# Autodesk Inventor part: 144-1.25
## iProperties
Created: 2007-06
Part Number: 144-1.25
Document SubType Name: Modeling
Designer: btaylor
Density: 1 g/cm^3
Author: btaylor
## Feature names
1. Extrusion1
2. Extrusion2
3. Extrusion3
4. Chamfer1
5. Chamfer2
6. Extrusion4
7. Extrusion5
8. Fillet1
9. Fillet2
